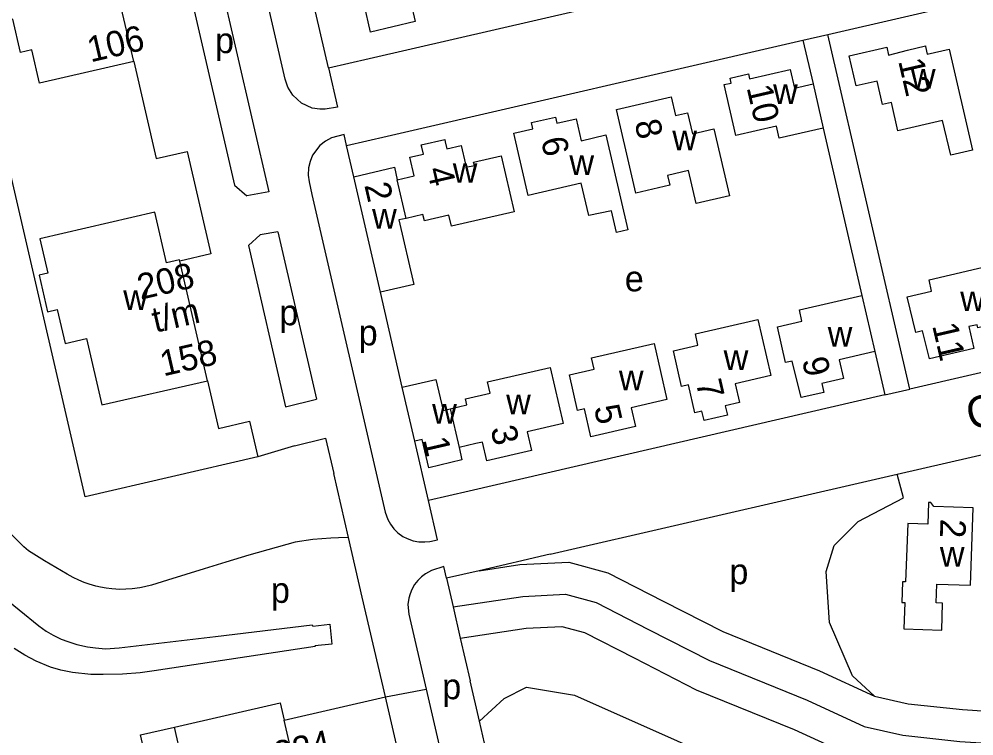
# Model space of a CAD drawing. Extents: x 155696 to 157795, y 382328 to 384028.
# Drawn here: x 156556.1 to 156705.6, y 383139.6 to 383251.7 of the extents above; entities that cross this region are included whole.
import ezdxf

# ---------------------------------------------------------------- set-up
doc = ezdxf.new("R2010")
doc.units = 0
for name, color, linetype in [('BLT_Basislijn', 7, 'Continuous'), ('BLT_Bebouwing', 7, 'Continuous'), ('BLT_Centroide', 7, 'Continuous'), ('BLT_Huisnummer', 7, 'Continuous'), ('BLT_Huisnummer_reeks', 7, 'Continuous'), ('BLT_Onderverdeling_panden', 7, 'Continuous'), ('BLT_Straatnaam', 7, 'Continuous'), ('BLT_Vlakafsluiter', 7, 'Continuous')]:
    doc.layers.add(name, color=color, linetype=linetype)

msp = doc.modelspace()

# ---------------------------------------------------------------- linework, layer by layer
at = {"layer": 'BLT_Basislijn'}
for p, q in [((156604.57, 383244.12), (156598.16, 383271.89)), ((156580.44, 383266.39), (156589.83, 383225.75)), ((156678.83, 383248.44), (156682.73, 383249.34)), ((156589.83, 383225.75), (156591.77, 383224.09)), ((156595.2, 383224.7), (156591.77, 383224.09)), ((156596.64, 383218.47), (156593.85, 383217.95)), ((156593.85, 383217.95), (156592.01, 383216.29)), ((156592.01, 383216.29), (156597.84, 383191.07)), ((156691.66, 383192.91), (156695.56, 383193.81)), ((156597.84, 383191.07), (156602.69, 383192.25)), ((156693.58, 383180.52), (156738.44, 383190.88)), ((156599.25, 383184.96), (156604.1, 383186.14)), ((156599.25, 383184.96), (156593.49, 383183.23)), ((156684.77, 383178.49), (156693.58, 383180.52)), ((156680.88, 383177.59), (156684.77, 383178.49)), ((156639.28, 383167.98), (156680.88, 383177.59)), ((156628.2, 383141.84), (156626.73, 383148.2)), ((156644.85, 383069.71), (156628.2, 383141.84))]:
    msp.add_line(p, q, dxfattribs=at)
for points in [[(156566.45, 383176.99), (156520.2, 383377.22)], [(156604.57, 383244.12), (156605.99, 383237.97), (156604.02, 383237.63), (156603.19, 383237.62), (156602.02, 383237.79), (156600.33, 383238.58), (156598.99, 383239.81), (156598.2, 383241.11), (156597.79, 383242.33), (156585.59, 383295.16), (156591.74, 383299.66)], [(156610.93, 383245.59), (156676, 383260.62), (156673.92, 383269.64)], [(156584.97, 383268.99), (156595.2, 383224.7)], [(156682.73, 383249.34), (156752.73, 383265.51), (156755.05, 383255.43)], [(156613.75, 383233.41), (156678.83, 383248.44), (156680.41, 383241.6)], [(156762.96, 383221.21), (156765.55, 383209.98), (156695.56, 383193.81), (156682.73, 383249.34)], [(156574.07, 383245.1), (156577.58, 383229.9), (156582.45, 383231.03), (156586.16, 383214.98), (156581.29, 383213.85)], [(156604.57, 383244.12), (156610.93, 383245.59)], [(156682.01, 383234.68), (156688.06, 383208.49)], [(156607.38, 383231.94), (156606.99, 383233.66), (156605.05, 383233.15), (156604.08, 383232.62), (156603.22, 383231.96), (156602.05, 383230.44), (156601.68, 383229.43), (156601.42, 383228.45), (156601.39, 383227.31), (156601.51, 383226.26), (156601.96, 383224.31), (156613.45, 383174.55), (156613.85, 383173.4), (156614.24, 383172.67), (156614.78, 383171.96), (156615.39, 383171.33), (156616.17, 383170.76), (156616.85, 383170.43), (156617.8, 383170.08), (156618.69, 383169.93), (156619.66, 383169.91), (156620.43, 383170), (156621.63, 383170.25), (156620.21, 383176.41)], [(156607.38, 383231.94), (156613.75, 383233.41)], [(156608.51, 383227.07), (156607.38, 383231.94)], [(156596.64, 383218.47), (156602.69, 383192.25)], [(156616.11, 383194.15), (156612.68, 383209.02)], [(156690.09, 383199.73), (156691.66, 383192.91), (156626.57, 383177.87)], [(156585.61, 383195.12), (156587.33, 383187.66), (156592.21, 383188.79), (156593.49, 383183.23)], [(156604.1, 383186.14), (156605.38, 383180.63)], [(156620.21, 383176.4), (156618.05, 383185.69)], [(156593.49, 383183.23), (156566.45, 383176.99)], [(156607.69, 383170.61), (156605.38, 383180.63)], [(156690.04, 383145.8), (156686.58, 383148.95), (156683, 383157.28), (156682.48, 383165.29), (156683.73, 383169.35), (156687.47, 383173.12), (156694.55, 383176.8), (156693.58, 383180.52)], [(156626.57, 383177.87), (156620.21, 383176.4)], [(156569.76, 383162.68), (156568.84, 383162.83), (156568.11, 383163.01), (156567.1, 383163.29), (156566.32, 383163.56), (156565.46, 383163.93), (156564.57, 383164.35), (156563.63, 383164.88), (156560.1, 383166.95), (156557.61, 383168.5), (156557.24, 383168.85), (156556.85, 383169.13), (156553.49, 383172.52)], [(156607.69, 383170.61), (156606.1, 383170.57), (156604.93, 383170.49), (156602.12, 383170.29), (156599.36, 383169.89), (156592.06, 383167.84), (156588.48, 383166.74), (156585.11, 383165.68), (156579.36, 383163.92), (156576.84, 383163.14), (156575.75, 383162.88), (156575.01, 383162.74), (156573.8, 383162.57), (156572.83, 383162.52), (156571.88, 383162.49), (156570.63, 383162.58), (156569.76, 383162.68)], [(156613.46, 383145.65), (156609.85, 383161.25), (156607.69, 383170.61)], [(156639.28, 383167.98), (156628.17, 383165.41)], [(156623.03, 383164.23), (156622.61, 383166.07), (156620.7, 383165.43), (156619.73, 383164.93), (156619.1, 383164.45), (156618.52, 383163.87), (156618.01, 383163.26), (156617.59, 383162.49), (156617.32, 383161.8), (156617.11, 383161.09), (156617, 383160.14), (156617.13, 383158.63), (156619.84, 383146.88)], [(156628.17, 383165.41), (156634.49, 383166.37), (156642.19, 383166.77), (156648.28, 383165.1), (156656.95, 383160.67), (156666.28, 383155.89), (156681.45, 383149.73), (156690.04, 383145.8)], [(156628.17, 383165.41), (156623.03, 383164.23)], [(156623.03, 383164.23), (156624.06, 383159.74)], [(156552.98, 383161.78), (156559.19, 383156.78), (156560.36, 383155.97), (156561.47, 383155.33), (156562.73, 383154.72), (156563.73, 383154.35), (156565.16, 383153.88), (156566.84, 383153.51), (156568.09, 383153.33), (156569.66, 383153.21), (156571.77, 383153.34), (156586.89, 383155.13), (156602.01, 383156.92)], [(156624.06, 383159.74), (156634.99, 383161.39), (156641.65, 383161.73), (156646.47, 383160.41), (156654.67, 383156.22), (156664.2, 383151.34), (156679.47, 383145.14), (156688.43, 383141.04), (156694.45, 383139.66), (156703.4, 383138.69), (156716.03, 383137.88), (156726.59, 383137.94), (156738.01, 383138.69), (156745.69, 383139.31), (156752.98, 383140.57)], [(156624.06, 383159.74), (156625.19, 383154.85)], [(156602.01, 383156.92), (156602.12, 383156.72), (156604.78, 383157.04), (156605.08, 383153.92)], [(156625.19, 383154.85), (156635.49, 383156.41), (156641.1, 383156.7), (156644.65, 383155.72), (156652.4, 383151.77), (156662.12, 383146.79), (156677.48, 383140.55), (156686.81, 383136.28), (156693.62, 383134.72), (156702.97, 383133.7), (156715.88, 383132.88), (156726.77, 383132.94), (156738.37, 383133.7), (156746.32, 383134.34), (156754.28, 383135.72), (156760.97, 383138.19), (156766.06, 383140.98), (156769.64, 383144.39), (156774.48, 383155.97)], [(156605.08, 383153.92), (156602.44, 383153.63), (156602.45, 383153.55)], [(156625.19, 383154.85), (156626.73, 383148.2)], [(156602.45, 383153.55), (156577.27, 383149.75), (156575.07, 383149.45), (156572.33, 383149.22), (156569.3, 383149.16), (156567.37, 383149.15), (156564.5, 383149.46), (156562.66, 383149.84), (156561.05, 383150.34), (156558.79, 383151.28), (156557, 383152.18), (156555.37, 383153.24)], [(156619.84, 383146.88), (156636.91, 383073.01), (156637.21, 383072.05), (156637.65, 383071.24), (156638.18, 383070.49), (156638.79, 383069.88), (156639.48, 383069.34), (156640.3, 383068.87), (156641.22, 383068.54), (156642.24, 383068.35), (156643.11, 383068.37), (156645.08, 383068.74), (156644.85, 383069.71)], [(156628.2, 383141.84), (156632.04, 383145.42), (156635.54, 383147.2), (156643.06, 383145.94), (156675.2, 383131.65), (156681.81, 383125.97), (156686.11, 383118.34), (156688.06, 383106.69), (156681.12, 383078.09)], [(156597.63, 383142), (156613.46, 383145.65)], [(156623.9, 383100.44), (156613.46, 383145.65)], [(156690.04, 383145.8), (156695.28, 383144.6), (156703.83, 383143.67), (156716.18, 383142.88), (156726.41, 383142.94), (156737.65, 383143.67), (156745.06, 383144.27), (156748.98, 383144.95)], [(156593.37, 383089.5), (156587, 383088.09), (156575.14, 383139.74), (156580.43, 383140.9)]]:
    msp.add_lwpolyline(points, dxfattribs=at)
at = {"layer": 'BLT_Bebouwing'}
for p, q in [((156574.07, 383245.1), (156569.74, 383263.84)), ((156585.61, 383195.12), (156581.29, 383213.85)), ((156584.1, 383125.38), (156580.43, 383140.9))]:
    msp.add_line(p, q, dxfattribs=at)
for points in [[(156607.11, 383261.86), (156619.11, 383264.7), (156619.09, 383264.81), (156620.04, 383265.04), (156622.38, 383255.42), (156617.46, 383254.28), (156618.13, 383251.36), (156611.13, 383249.7), (156610.12, 383254.05)], [(156574.07, 383245.1), (156559.31, 383241.69), (156558.1, 383246.91), (156556.35, 383246.51), (156555.14, 383251.73), (156551.78, 383250.95)], [(156686.07, 383246.01), (156691.94, 383247.36), (156692.23, 383246.1), (156695.21, 383246.9), (156698, 383247.54), (156698.02, 383247.44), (156698.3, 383246.24), (156701.73, 383247.03)], [(156701.73, 383247.03), (156705.38, 383231.22), (156701.96, 383230.43), (156700.7, 383235.87), (156693.71, 383234.26), (156692.69, 383238.69), (156691.28, 383238.36), (156690.43, 383242.05), (156687.15, 383241.29), (156686.07, 383246.01)], [(156682.01, 383234.68), (156675.13, 383233.09), (156674.7, 383234.97), (156668.33, 383233.5), (156666.48, 383241.49), (156667.61, 383241.73), (156667.43, 383242.51), (156670.29, 383243.18), (156670.48, 383242.4), (156676.81, 383243.87), (156677.49, 383240.92), (156680.41, 383241.6)], [(156680.41, 383241.6), (156682.01, 383234.68)], [(156660.94, 383228.02), (156657.64, 383227.25), (156658, 383225.73), (156652.67, 383224.48), (156652.02, 383227.23), (156649.62, 383237.59), (156658.2, 383239.57), (156658.87, 383236.65), (156660.76, 383237.08), (156661.52, 383233.77), (156664.9, 383234.55), (156667.32, 383224.09), (156662.11, 383222.88), (156660.94, 383228.02)], [(156633.59, 383233.89), (156636.57, 383234.56), (156636.35, 383235.53), (156640.09, 383236.39), (156640.31, 383235.43), (156643.33, 383236.14), (156644.12, 383232.71), (156647.98, 383233.6), (156651.44, 383218.75)], [(156644.12, 383226.06), (156635.84, 383224.14), (156633.59, 383233.89)], [(156615.32, 383226.59), (156617.95, 383227.2), (156617.28, 383230.12), (156619.42, 383230.61), (156619.18, 383231.69), (156619.09, 383232.06), (156622.75, 383232.9), (156622.83, 383232.53), (156623.08, 383231.46), (156625.32, 383231.98), (156625.99, 383229.05), (156626.07, 383228.54), (156627.39, 383228.84), (156627.27, 383229.33), (156631.59, 383230.35), (156633.62, 383221.58), (156623.83, 383219.32), (156623.42, 383221.07), (156619.57, 383220.18), (156619.35, 383221.15), (156616.72, 383220.54)], [(156608.51, 383227.07), (156614.87, 383228.54), (156615.32, 383226.59)], [(156612.68, 383209.02), (156608.51, 383227.07)], [(156651.44, 383218.75), (156649.63, 383218.33), (156648.84, 383221.75), (156645.29, 383221), (156644.12, 383226.06)], [(156581.29, 383213.85), (156581.24, 383214.04), (156579.19, 383213.57), (156577.36, 383221.53), (156559.38, 383217.37), (156560.63, 383211.97), (156559.24, 383211.65)], [(156616.72, 383220.54), (156615.57, 383220.31), (156617.93, 383210.22), (156612.68, 383209.02)], [(156559.24, 383211.65), (156560.56, 383205.91), (156562.1, 383206.27), (156563.33, 383200.97)], [(156690.09, 383199.73), (156684.48, 383198.43), (156685.16, 383195.51), (156681.78, 383194.7), (156682.08, 383193.31), (156678.56, 383192.5), (156677.16, 383198.22), (156676.08, 383197.97), (156674.83, 383203.59), (156678.67, 383204.48), (156678.27, 383206.23), (156688.06, 383208.49)], [(156688.06, 383208.49), (156690.09, 383199.73)], [(156563.33, 383200.97), (156566.69, 383201.74), (156569.07, 383191.39), (156585.61, 383195.12)], [(156623.6, 383190.74), (156626.23, 383191.35), (156626.01, 383192.32), (156629.86, 383193.2), (156629.45, 383194.96), (156639.24, 383197.22), (156641.27, 383188.45), (156635.67, 383187.16), (156636.34, 383184.23), (156629.36, 383182.59), (156628.69, 383185.52), (156627.63, 383185.3), (156625, 383184.69)], [(156616.11, 383194.15), (156621.37, 383195.33), (156622.5, 383190.46), (156623.6, 383190.74)], [(156618.05, 383185.69), (156616.11, 383194.15)], [(156625, 383184.69), (156625.45, 383182.74), (156620.26, 383181.49), (156619.22, 383185.96), (156618.05, 383185.69)], [(156694.64, 383156.3), (156700.55, 383156.11), (156700.69, 383160.35), (156699.69, 383160.38), (156699.78, 383163.3), (156705.07, 383163.13), (156705.5, 383175.24)], [(156705.5, 383175.24), (156699.31, 383175.46), (156698.86, 383176.07), (156698.48, 383176.09), (156698.36, 383172.68), (156695.24, 383172.78)], [(156695.24, 383172.78), (156694.88, 383163.66), (156694.41, 383163.68), (156694.31, 383160.45), (156694.78, 383160.43), (156694.64, 383156.3)], [(156580.43, 383140.9), (156597, 383144.73), (156597.63, 383142)], [(156584.1, 383125.38), (156600.59, 383129.16), (156597.63, 383142)]]:
    msp.add_lwpolyline(points, dxfattribs=at)
for points in [[(156695.15, 383208.27), (156698.98, 383209.15), (156698.57, 383210.95), (156709.48, 383213.47), (156711.51, 383204.68), (156706.23, 383203.43), (156706.12, 383203.91), (156704.8, 383203.61), (156705.58, 383200.2), (156698.62, 383198.59), (156697.57, 383202.95), (156696.5, 383202.69)], [(156658.55, 383199.83), (156662.4, 383200.72), (156662, 383202.48), (156671.79, 383204.74), (156673.81, 383195.97), (156668.21, 383194.67), (156668.89, 383191.75), (156666.67, 383191.22), (156667, 383189.76), (156663.35, 383188.91), (156663.01, 383190.37), (156661.89, 383190.12), (156660.9, 383194.49), (156659.83, 383194.24)], [(156642.28, 383196.07), (156646.13, 383196.96), (156645.73, 383198.72), (156655.52, 383200.98), (156657.54, 383192.21), (156651.94, 383190.92), (156652.62, 383187.99), (156645.62, 383186.35), (156644.63, 383190.72), (156643.56, 383190.47)]]:
    msp.add_lwpolyline(points, close=True, dxfattribs=at)
at = {"layer": 'BLT_Onderverdeling_panden'}
for p, q in [((156616.72, 383220.54), (156615.32, 383226.59)), ((156623.6, 383190.74), (156625, 383184.69))]:
    msp.add_line(p, q, dxfattribs=at)
at = {"layer": 'BLT_Vlakafsluiter'}
msp.add_line((156613.46, 383145.65), (156619.84, 383146.88), dxfattribs=at)

# ---------------------------------------------------------------- texts
at = {"layer": 'BLT_Centroide'}
for s, p in [('p', (156586.79, 383246.41)), ('w', (156695.73, 383240.84)), ('w', (156674.16, 383238.47)), ('w', (156658.38, 383231.22)), ('w', (156642.27, 383227.34)), ('w', (156624.01, 383226.12)), ('w', (156611.38, 383218.94)), ('e', (156650.94, 383209.13)), ('w', (156572.42, 383206.22)), ('w', (156703.45, 383206.03)), ('p', (156596.86, 383203.82)), ('p', (156609.28, 383200.68)), ('w', (156682.71, 383200.5)), ('w', (156666.42, 383196.81)), ('w', (156650.02, 383193.66)), ('w', (156632.37, 383189.91)), ('w', (156620.78, 383188.41)), ('w', (156700.27, 383166.06)), ('p', (156667.31, 383163.3)), ('p', (156595.54, 383160.38)), ('p', (156622.36, 383145.3))]:
    msp.add_text(s, height=4, dxfattribs=at).set_placement(p)
at = {"layer": 'BLT_Huisnummer'}
for s, rotation, p in [('12', 283.0031, (156693.73, 383245.19)), ('10', 283.0031, (156670, 383241.03)), ('8', 283.0031, (156652.44, 383235.59)), ('6', 283.0092, (156637.78, 383232.87)), ('4', 283.0097, (156619.94, 383228.22)), ('2', 283.0097, (156610.15, 383225.75)), ('11', 283.0102, (156699.05, 383203.78)), ('9', 283.0072, (156678.65, 383198.4)), ('7', 283.0072, (156662.04, 383194.91)), ('5', 283.0072, (156646.08, 383190.95)), ('3', 283.0072, (156629.9, 383187.67)), ('1', 283.0072, (156619.29, 383185.92)), ('2', 268.0059, (156700.38, 383173.56))]:
    msp.add_text(s, height=4, rotation=rotation, dxfattribs=at).set_placement(p)
at = {"layer": 'BLT_Huisnummer_reeks'}
for s, rotation, p in [('106', 13.0058, (156567.31, 383244.96)), ('208', 13.0058, (156575.14, 383207.8)), ('t/m', 13.0058, (156577.45, 383202.64)), ('158', 13.0058, (156578.71, 383195.81)), ('210t/m224', 13.0091, (156580.61, 383130.98))]:
    msp.add_text(s, height=4, rotation=rotation, dxfattribs=at).set_placement(p)
at = {"layer": 'BLT_Straatnaam'}
msp.add_text('GRASLEEUWERIK', height=5, rotation=13.0069, dxfattribs=at).set_placement((156705.05, 383187.35))

doc.saveas('drawing.dxf')
